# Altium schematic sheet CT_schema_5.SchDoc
size 218 x 258 mm
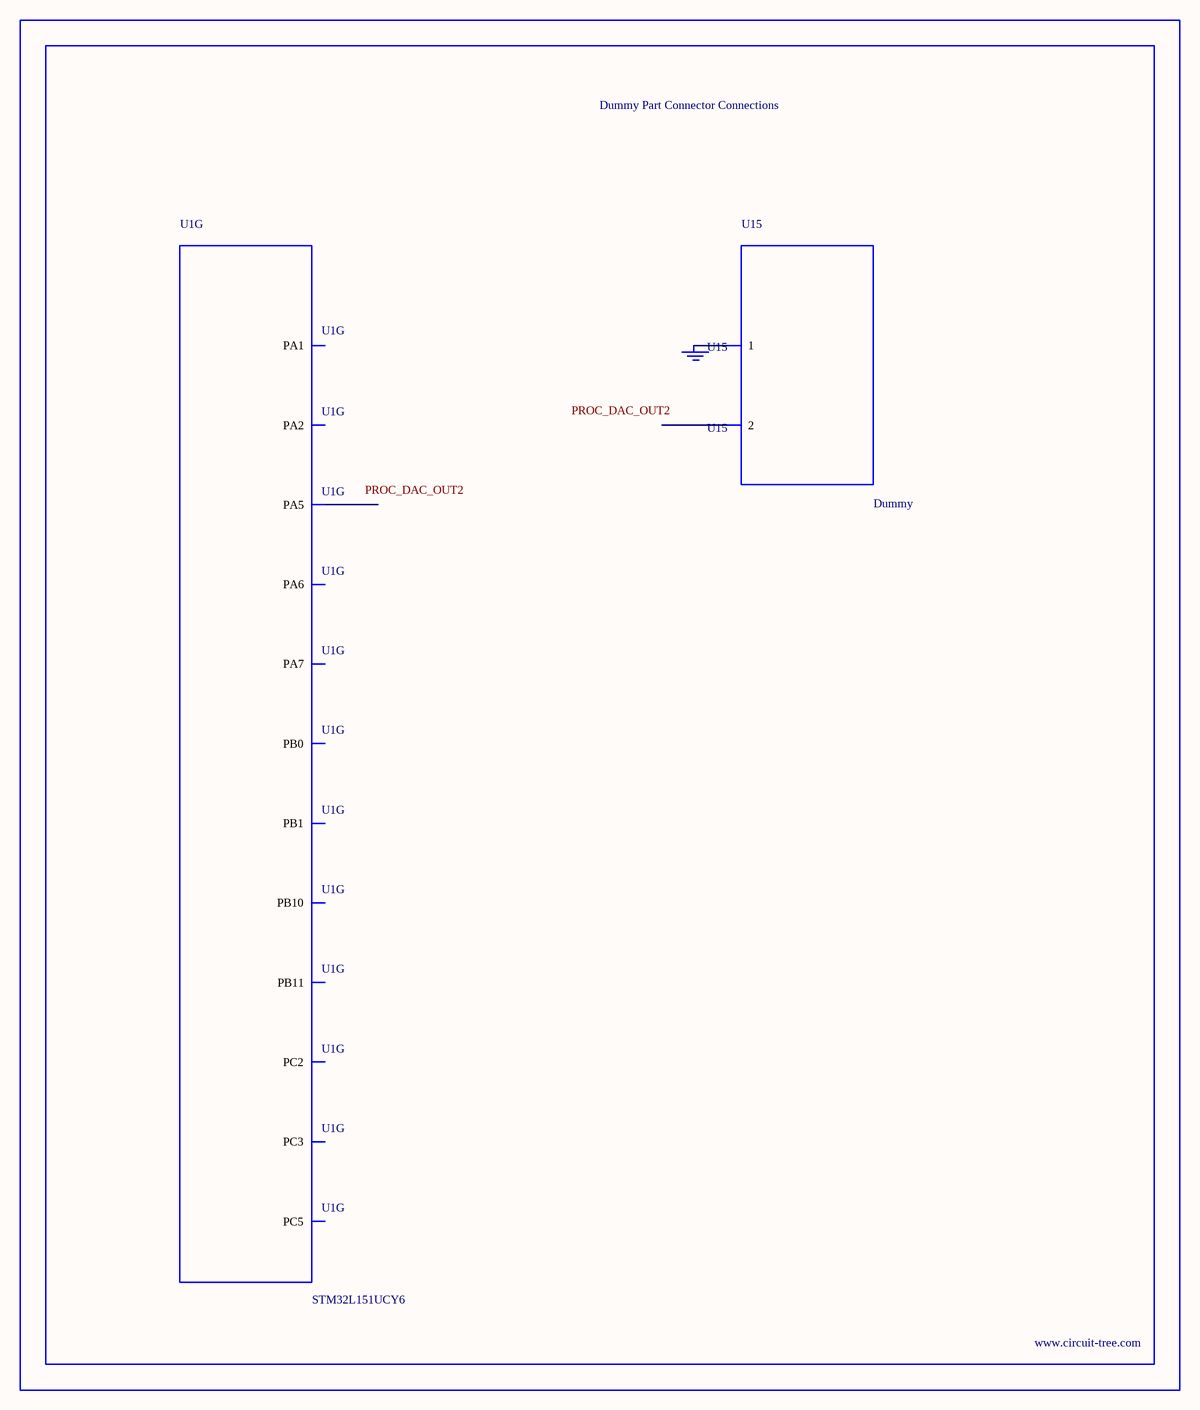
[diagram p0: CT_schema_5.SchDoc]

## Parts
BORDER4  (no value)
GND_INSTANCE_4_0  (no value)
U1  STM32L151UCY6  [WLCSP63]  (part G of 7)
U15  Dummy  [DUMMY_PACKAGE_118]

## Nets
NetGND_INSTANCE_4_0_0: GND_INSTANCE_4_0.0(GND) U15.1

Not connected (* = marked no-connect by the designer): U1 G4(PA6) G5(PA1) G6(PC3) G7(PC2) H2(PB11) H3(PB1) H4(PA5) H6(PA2) J2(PB10) J3(PB0) J4(PC5) J5(PA7); U15 2

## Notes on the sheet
- Labels drawn without touching a wire or pin: PROC_DAC_OUT2

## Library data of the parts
BORDER4 = BORDER_PAGE4
GND_INSTANCE_4_0 = GND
